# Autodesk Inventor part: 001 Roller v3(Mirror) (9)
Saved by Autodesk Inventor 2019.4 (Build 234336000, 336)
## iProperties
Created: 2020-06
Part Number: 001 Roller v3(Mirror) (9)
Material: Generic
Document SubType Name: Modeling
Designer: Administrator
Density: 1 g/cm^3
Appearance: Default
Title: 001 Roller v3(Mirror) (9)
Author: Administrator
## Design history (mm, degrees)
